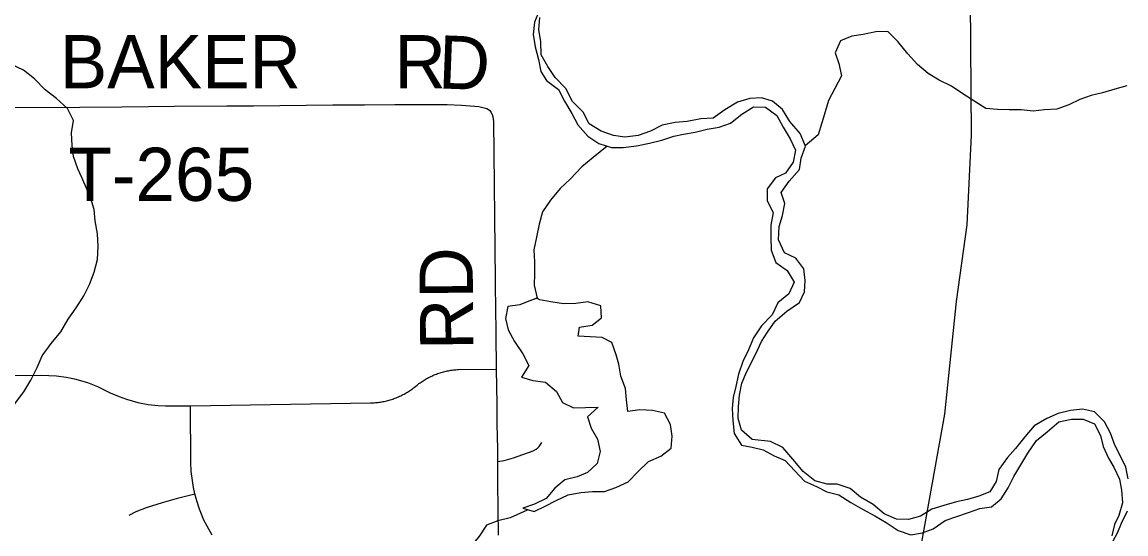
# Model space of a CAD drawing. Extents: x 0 to 34, y 0 to 22.
# Drawn here: x 4.301 to 4.89, y 17.083 to 17.356 of the extents above; entities that cross this region are included whole.
import ezdxf

# ---------------------------------------------------------------- set-up
doc = ezdxf.new("R2010")
doc.units = 0
for name, color, linetype in [('GM_X_Major_River', 7, 'Continuous'), ('GM_X_Minor_Lake', 7, 'Continuous'), ('GM_X_Minor_River', 7, 'Continuous'), ('GM_X_Rail_Line', 7, 'Continuous'), ('GM_X_Township_Road', 7, 'Continuous'), ('GM_X_Township_Road_Text', 7, 'Continuous')]:
    doc.layers.add(name, color=color, linetype=linetype)

msp = doc.modelspace()

# ---------------------------------------------------------------- linework, layer by layer
at = {"layer": 'GM_X_Major_River'}
for points in [[(4.57723, 17.36239), (4.57459, 17.35593), (4.57384, 17.34929), (4.57498, 17.34284), (4.57669, 17.33601), (4.57802, 17.32956), (4.58106, 17.32482), (4.5875, 17.31989), (4.59072, 17.31382), (4.59452, 17.30719), (4.59774, 17.30112), (4.60305, 17.29505), (4.60892, 17.29107), (4.61574, 17.28899), (4.62199, 17.289), (4.62918, 17.28995), (4.63599, 17.29129), (4.64262, 17.293), (4.64905, 17.29509), (4.65416, 17.29605), (4.66041, 17.29719), (4.66684, 17.29871), (4.67328, 17.29986), (4.67934, 17.30195), (4.68539, 17.30689), (4.69163, 17.31069), (4.69807, 17.31051), (4.70413, 17.30615), (4.70736, 17.29989), (4.71115, 17.29363), (4.714, 17.28756), (4.71268, 17.28111), (4.70871, 17.27522), (4.70341, 17.27275), (4.69887, 17.26687), (4.69888, 17.2606), (4.7021, 17.25435), (4.70078, 17.24751), (4.70079, 17.24106), (4.70098, 17.23423), (4.70345, 17.22759), (4.70951, 17.22323), (4.7133, 17.21717), (4.71047, 17.2109)], [(4.57723, 17.36239), (4.57459, 17.35593), (4.57384, 17.34929), (4.57498, 17.34284), (4.57669, 17.33601), (4.57802, 17.32956), (4.58106, 17.32482), (4.5875, 17.31989), (4.59072, 17.31382), (4.59452, 17.30719), (4.59774, 17.30112), (4.60305, 17.29505), (4.60892, 17.29107), (4.61574, 17.28899), (4.62199, 17.289), (4.62918, 17.28995), (4.63599, 17.29129), (4.64262, 17.293), (4.64905, 17.29509), (4.65416, 17.29605), (4.66041, 17.29719), (4.66684, 17.29871), (4.67328, 17.29986), (4.67934, 17.30195), (4.68539, 17.30689), (4.69163, 17.31069), (4.69807, 17.31051), (4.70413, 17.30615), (4.70736, 17.29989), (4.71115, 17.29363), (4.714, 17.28756), (4.71268, 17.28111), (4.70871, 17.27522), (4.70341, 17.27275), (4.69887, 17.26687), (4.69888, 17.2606), (4.7021, 17.25435), (4.70078, 17.24751), (4.70079, 17.24106), (4.70098, 17.23423), (4.70345, 17.22759), (4.70951, 17.22323), (4.7133, 17.21717), (4.71047, 17.2109)], [(4.78687, 17.09579), (4.78082, 17.09218), (4.77438, 17.09027), (4.76795, 17.09046), (4.76132, 17.0933), (4.75545, 17.09842), (4.74881, 17.1022), (4.74313, 17.10694), (4.73631, 17.10921), (4.73101, 17.10921), (4.72439, 17.11091), (4.71813, 17.11603), (4.71264, 17.12248), (4.70733, 17.12873), (4.7007, 17.13195), (4.69086, 17.13308), (4.68517, 17.13801), (4.68346, 17.14427), (4.68364, 17.15072), (4.68402, 17.1568), (4.68534, 17.16306), (4.68779, 17.16894), (4.69082, 17.17483), (4.69365, 17.18071), (4.69592, 17.18546), (4.69913, 17.1904), (4.7031, 17.19628), (4.70934, 17.2016), (4.71616, 17.20616), (4.7188, 17.21186), (4.71917, 17.21793), (4.71841, 17.22419), (4.71424, 17.22988), (4.70818, 17.23272), (4.70495, 17.23974), (4.70533, 17.24676), (4.70702, 17.25264), (4.70834, 17.2591), (4.70644, 17.26498), (4.7106, 17.27105), (4.71609, 17.27732), (4.71703, 17.28339), (4.71929, 17.28966), (4.71645, 17.29648), (4.71095, 17.30293), (4.70716, 17.30938), (4.70166, 17.31374), (4.69579, 17.31544), (4.68955, 17.31524), (4.68311, 17.31315), (4.6763, 17.30916), (4.67006, 17.3046), (4.66343, 17.3044), (4.65624, 17.30288), (4.6498, 17.3023), (4.6428, 17.30097), (4.63655, 17.29774), (4.62993, 17.29546), (4.62293, 17.2945), (4.61687, 17.29544), (4.61024, 17.29771), (4.6038, 17.30169), (4.60057, 17.30795), (4.59489, 17.31364), (4.59128, 17.32046), (4.5856, 17.32634), (4.58181, 17.33222), (4.57821, 17.33848), (4.57801, 17.3455), (4.57687, 17.35195), (4.57743, 17.3584)], [(4.71047, 17.2109), (4.70461, 17.20596), (4.70158, 17.1997), (4.69591, 17.19381), (4.69156, 17.18735), (4.68892, 17.1809), (4.68589, 17.17463), (4.68363, 17.16799), (4.68212, 17.16135), (4.6808, 17.15546), (4.68024, 17.14958), (4.68062, 17.14313), (4.6812, 17.1363), (4.68518, 17.13004), (4.69086, 17.12891), (4.69673, 17.12759), (4.7026, 17.12436), (4.70847, 17.1219), (4.71359, 17.11641), (4.7189, 17.11072), (4.72515, 17.10788), (4.73083, 17.10503), (4.73708, 17.10352), (4.74352, 17.09935), (4.74977, 17.09594), (4.7564, 17.09234), (4.76246, 17.08874), (4.7689, 17.08439), (4.77553, 17.08211), (4.78177, 17.08326), (4.78745, 17.08535), (4.79389, 17.08972), (4.80013, 17.092), (4.80638, 17.0941), (4.81243, 17.09619), (4.81868, 17.09714), (4.82379, 17.10132), (4.82757, 17.10721), (4.83059, 17.11328), (4.83815, 17.12582), (4.84269, 17.13246), (4.84836, 17.13721), (4.85461, 17.14253), (4.86142, 17.14387), (4.86767, 17.14387), (4.87373, 17.14141), (4.87695, 17.13515), (4.87828, 17.12927), (4.88113, 17.12301), (4.88397, 17.11827), (4.88701, 17.11182), (4.88815, 17.10594), (4.88872, 17.0993), (4.88665, 17.09246), (4.88438, 17.08772), (4.88287, 17.08164)], [(4.89174, 17.11201), (4.89041, 17.11827), (4.88813, 17.12302), (4.88453, 17.13003), (4.88225, 17.13648), (4.87903, 17.14255), (4.87372, 17.14786), (4.86728, 17.14918), (4.86085, 17.14861), (4.85422, 17.14689), (4.84817, 17.14423), (4.84155, 17.14043), (4.83644, 17.13454), (4.83152, 17.12828), (4.82717, 17.12353), (4.82264, 17.11707), (4.82113, 17.11062), (4.81772, 17.10511), (4.81186, 17.10283), (4.8058, 17.10093), (4.79993, 17.09978), (4.79331, 17.09788), (4.78687, 17.09579)], [(4.88344, 17.07861), (4.88609, 17.08354), (4.88817, 17.08829), (4.89138, 17.09493)]]:
    msp.add_lwpolyline(points, dxfattribs=at)
at = {"layer": 'GM_X_Minor_Lake'}
for points in [[(4.57601, 17.20848), (4.57167, 17.207), (4.56685, 17.20497), (4.56042, 17.20402), (4.5591, 17.19776), (4.56061, 17.19169), (4.56402, 17.18543), (4.56837, 17.17879), (4.57159, 17.17254), (4.56762, 17.16628), (4.57368, 17.16457), (4.58049, 17.16363), (4.58635, 17.1587), (4.58957, 17.15282), (4.59544, 17.14998), (4.60187, 17.15017), (4.60868, 17.15036), (4.603, 17.14524), (4.6049, 17.13917), (4.6083, 17.13329), (4.60963, 17.12665), (4.60812, 17.1202), (4.60302, 17.11546), (4.59734, 17.11318), (4.59091, 17.11147), (4.58543, 17.1071), (4.58089, 17.1016), (4.57465, 17.09856), (4.56841, 17.09647), (4.57446, 17.09457), (4.58033, 17.09742), (4.58619, 17.10046)], [(4.57597, 17.20847), (4.57167, 17.207), (4.56685, 17.20497), (4.56042, 17.20402), (4.5591, 17.19776), (4.56061, 17.19169), (4.56402, 17.18543), (4.56837, 17.17879), (4.57159, 17.17254), (4.56762, 17.16628), (4.57368, 17.16457), (4.58049, 17.16363), (4.58635, 17.1587), (4.58957, 17.15282), (4.59544, 17.14998), (4.60187, 17.15017), (4.60868, 17.15036), (4.603, 17.14524), (4.6049, 17.13917), (4.6083, 17.13329), (4.60963, 17.12665), (4.60812, 17.1202), (4.60302, 17.11546), (4.59734, 17.11318), (4.59091, 17.11147), (4.58543, 17.1071), (4.58089, 17.1016), (4.57465, 17.09856), (4.56841, 17.09647), (4.57446, 17.09457), (4.58033, 17.09742), (4.58619, 17.10046)], [(4.58619, 17.10046), (4.59262, 17.1035), (4.59943, 17.10483), (4.60567, 17.10521), (4.6121, 17.10522), (4.61815, 17.1075), (4.62458, 17.11053), (4.62987, 17.11585), (4.63555, 17.12135), (4.64217, 17.1242), (4.64765, 17.12838), (4.64821, 17.13483), (4.64727, 17.14109), (4.64405, 17.14716), (4.63762, 17.14848), (4.63081, 17.14886), (4.62456, 17.14809), (4.62381, 17.15416), (4.62324, 17.16023), (4.62077, 17.16687), (4.61964, 17.17332), (4.61831, 17.17825), (4.61585, 17.18489), (4.61074, 17.18754), (4.59788, 17.18829), (4.59863, 17.19304), (4.60544, 17.19418), (4.61036, 17.19798), (4.60998, 17.20442), (4.60317, 17.20651), (4.59673, 17.20574), (4.59011, 17.20555), (4.5833, 17.2065), (4.57755, 17.20768), (4.57574, 17.20858)], [(4.58619, 17.10046), (4.59262, 17.1035), (4.59943, 17.10483), (4.60567, 17.10521), (4.6121, 17.10522), (4.61815, 17.1075), (4.62458, 17.11053), (4.62987, 17.11585), (4.63555, 17.12135), (4.64217, 17.1242), (4.64765, 17.12838), (4.64821, 17.13483), (4.64727, 17.14109), (4.64405, 17.14716), (4.63762, 17.14848), (4.63081, 17.14886), (4.62456, 17.14809), (4.62381, 17.15416), (4.62324, 17.16023), (4.62077, 17.16687), (4.61964, 17.17332), (4.61831, 17.17825), (4.61585, 17.18489), (4.61074, 17.18754), (4.59788, 17.18829), (4.59863, 17.19304), (4.60544, 17.19418), (4.61036, 17.19798), (4.60998, 17.20442), (4.60317, 17.20651), (4.59673, 17.20574), (4.59011, 17.20555), (4.5833, 17.2065), (4.57755, 17.20768), (4.57597, 17.20847)]]:
    msp.add_lwpolyline(points, dxfattribs=at)
at = {"layer": 'GM_X_Minor_River'}
for points in [[(4.89089, 17.322), (4.8845, 17.32014), (4.87793, 17.31828), (4.87191, 17.31681), (4.86591, 17.31459), (4.85992, 17.3118), (4.85355, 17.30956), (4.84694, 17.30903), (4.8409, 17.30832), (4.83446, 17.30912), (4.82803, 17.30916), (4.82197, 17.30921), (4.81572, 17.30982), (4.80977, 17.31348), (4.80344, 17.3177), (4.79729, 17.32173), (4.79079, 17.32499), (4.78484, 17.32846), (4.77925, 17.33326), (4.77401, 17.33902), (4.76875, 17.34554), (4.76333, 17.35092), (4.75691, 17.35077), (4.75014, 17.34928), (4.7441, 17.34838), (4.73811, 17.34597), (4.73523, 17.33964), (4.73707, 17.3338), (4.73854, 17.3272), (4.7351, 17.32048), (4.73166, 17.31414), (4.72991, 17.30803), (4.72815, 17.30211), (4.72603, 17.2958), (4.71923, 17.28992)], [(4.32986, 17.20332), (4.33401, 17.2098), (4.33702, 17.2159), (4.33946, 17.22237), (4.34133, 17.22923), (4.34167, 17.23607), (4.34126, 17.24292), (4.34009, 17.24976), (4.33949, 17.25584), (4.33775, 17.26173), (4.33583, 17.26648), (4.33295, 17.27293), (4.33084, 17.27768), (4.32853, 17.28414), (4.32774, 17.29003), (4.32733, 17.29687), (4.32843, 17.30334), (4.32517, 17.30979), (4.31945, 17.3151), (4.31335, 17.31983), (4.30762, 17.3257), (4.30171, 17.33025), (4.29505, 17.33345)], [(4.61352, 17.28966), (4.60604, 17.28373), (4.59992, 17.27865), (4.59364, 17.27206), (4.58827, 17.26719), (4.58312, 17.26081), (4.57891, 17.25465), (4.57718, 17.24797), (4.57563, 17.2411), (4.57427, 17.23443), (4.57461, 17.22799), (4.57457, 17.22154), (4.57452, 17.21546), (4.57601, 17.20848)], [(4.25162, 17.08133), (4.25425, 17.08723), (4.25726, 17.09409), (4.26366, 17.10666), (4.26743, 17.11219), (4.27101, 17.11791), (4.27516, 17.12382), (4.27893, 17.13011), (4.28213, 17.13659), (4.28552, 17.14135), (4.29158, 17.14613), (4.29687, 17.15186), (4.30197, 17.15853), (4.30574, 17.16482), (4.30912, 17.17149), (4.31175, 17.17777), (4.31647, 17.18426), (4.32176, 17.19055), (4.32552, 17.19741), (4.32986, 17.20332)], [(4.57075, 17.09535), (4.56169, 17.09129), (4.55511, 17.08962), (4.54892, 17.08739), (4.54491, 17.08103), (4.53957, 17.07484), (4.53279, 17.07354), (4.52659, 17.07188), (4.52042, 17.0687), (4.51487, 17.06345), (4.51255, 17.05714), (4.51441, 17.05035), (4.51362, 17.04388), (4.51264, 17.03722), (4.51164, 17.03113), (4.50802, 17.02421), (4.50533, 17.01789), (4.50359, 17.01121), (4.49978, 17.00429), (4.49634, 16.99776)]]:
    msp.add_lwpolyline(points, dxfattribs=at)
at = {"layer": 'GM_X_Rail_Line'}
msp.add_lwpolyline([(4.76791, 17.00293), (4.79375, 17.14663), (4.79991, 17.2068), (4.80568, 17.24767), (4.80796, 17.29563), (4.80745, 17.36765), (4.80531, 17.38086), (4.79833, 17.40059), (4.77663, 17.43675), (4.76364, 17.46488), (4.7557, 17.50103), (4.75403, 17.51651), (4.75612, 17.80268), (4.75391, 18.09859), (4.74923, 18.38092), (4.74367, 18.7078), (4.73815, 19.14265), (4.73332, 19.55441), (4.7315, 19.92628), (4.72821, 20.24009), (4.74767, 20.27759), (4.79462, 20.37419), (4.79387, 20.42708)], dxfattribs=at)
at = {"layer": 'GM_X_Township_Road'}
for points in [[(4.29159, 17.3104), (4.33185, 17.31049), (4.35423, 17.31069), (4.36842, 17.31082), (4.38219, 17.311), (4.41034, 17.3112), (4.42453, 17.31133), (4.43865, 17.31146), (4.45275, 17.31158), (4.46694, 17.31171), (4.48379, 17.31178), (4.50009, 17.31197), (4.52808, 17.31196), (4.53568, 17.31163), (4.54488, 17.31087), (4.54923, 17.30977), (4.55054, 17.30892), (4.55135, 17.30809)], [(4.55536, 17.08191), (4.55518, 17.09587), (4.55511, 17.11003), (4.55509, 17.12132), (4.55499, 17.128), (4.55478, 17.14131), (4.55464, 17.15188), (4.55439, 17.17071), (4.55413, 17.1897), (4.55394, 17.20399), (4.5538, 17.21458), (4.55375, 17.21818), (4.55288, 17.3029), (4.55255, 17.30533), (4.55226, 17.30644), (4.55135, 17.30809)], [(4.29272, 17.16718), (4.3108, 17.16736), (4.31524, 17.1673), (4.31939, 17.16699), (4.32451, 17.1663), (4.32905, 17.16542), (4.33595, 17.16342), (4.34121, 17.16133), (4.3481, 17.15807), (4.35278, 17.15598), (4.35681, 17.15453), (4.36275, 17.15275), (4.36828, 17.15173), (4.3737, 17.15121), (4.37761, 17.15109), (4.39096, 17.15102), (4.48709, 17.15262), (4.48909, 17.1527), (4.48976, 17.15275), (4.49042, 17.15281), (4.49109, 17.15289), (4.49175, 17.15297), (4.49241, 17.15307), (4.49307, 17.15317), (4.49373, 17.15329), (4.49439, 17.15342), (4.49504, 17.15356), (4.49569, 17.15371), (4.49634, 17.15388), (4.49698, 17.15405), (4.49763, 17.15424), (4.49827, 17.15444), (4.4989, 17.15465), (4.49953, 17.15487), (4.50016, 17.1551), (4.50078, 17.15534), (4.5014, 17.15559), (4.50201, 17.15585), (4.50262, 17.15613), (4.50323, 17.15641), (4.50383, 17.1567), (4.50442, 17.15701), (4.50501, 17.15732), (4.50559, 17.15765), (4.50617, 17.15798), (4.50674, 17.15833), (4.5073, 17.15868), (4.50786, 17.15905), (4.50841, 17.15942), (4.50896, 17.1598), (4.5095, 17.1602), (4.51003, 17.1606), (4.51055, 17.16101), (4.51119, 17.16153), (4.51189, 17.1621), (4.51242, 17.16251), (4.51295, 17.16292), (4.51349, 17.16331), (4.51403, 17.16369), (4.51459, 17.16406), (4.51515, 17.16443), (4.51571, 17.16478), (4.51628, 17.16512), (4.51686, 17.16546), (4.51744, 17.16578), (4.51803, 17.1661), (4.51862, 17.1664), (4.51922, 17.16669), (4.51982, 17.16697), (4.52043, 17.16724), (4.52105, 17.16751), (4.52167, 17.16776), (4.52229, 17.168), (4.52291, 17.16823), (4.52354, 17.16845), (4.52418, 17.16865), (4.52481, 17.16885), (4.52545, 17.16903), (4.5261, 17.16921), (4.52674, 17.16937), (4.52739, 17.16952), (4.52804, 17.16966), (4.5287, 17.16979), (4.52936, 17.16991), (4.53001, 17.17002), (4.53067, 17.17011), (4.53133, 17.17019), (4.532, 17.17026), (4.53266, 17.17033), (4.53332, 17.17038), (4.53399, 17.17041), (4.55439, 17.17071)], [(4.40259, 17.08192), (4.40069, 17.08512), (4.39801, 17.09004), (4.39638, 17.09404), (4.39571, 17.09579), (4.39433, 17.10032), (4.39323, 17.10398), (4.39248, 17.1075), (4.39195, 17.11111), (4.39133, 17.11603), (4.39105, 17.12099), (4.39096, 17.15102)], [(4.55509, 17.12132), (4.55843, 17.12193), (4.56339, 17.12332), (4.57397, 17.12704), (4.5755, 17.12791), (4.57645, 17.12864), (4.5771, 17.1293), (4.5779, 17.13039), (4.57849, 17.13141)], [(4.35817, 17.09268), (4.36194, 17.09457), (4.36748, 17.09666), (4.37597, 17.09949), (4.38473, 17.10189), (4.39323, 17.10398)]]:
    msp.add_lwpolyline(points, dxfattribs=at)

# ---------------------------------------------------------------- texts
at = {"layer": 'GM_X_Township_Road_Text'}
for s, height, rotation, p in [('BAKER', 0.028409, 0.00001, (4.32112, 17.32061)), ('R', 0.02841, 359.98439, (4.49987, 17.32061)), ('D', 0.02841, 357.7883, (4.52291, 17.32061)), ('T-265', 0.028409, 0.00001, (4.3257, 17.26048)), ('RD', 0.028409, 90.49365, (4.54203, 17.18095))]:
    msp.add_text(s, height=height, rotation=rotation, dxfattribs=at).set_placement(p)

doc.saveas('drawing.dxf')
